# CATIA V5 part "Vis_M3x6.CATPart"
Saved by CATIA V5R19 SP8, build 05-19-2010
Part number: Vis M3x6
Nomenclature:  MAKER100359
Publications: "Mating Face", "Axis"
Bounding box of the stored display mesh (mm): x -6 to 1.764, y -3.2 to 3.2, z -3.2 to 3.2
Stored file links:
  D:\Documents\1_Travail\1 - ac-limoges.fr\ac-limoges.fr\Emmanuel Maynard - STI2D_Turgot\1 - IT-I2D\Activités_IT_Première\IT_3_Abris_bus\Maquettes numériques\Abribus_eleve\Vis_M3x6.CATPart
  C:\Program Files\Dassault Systemes\B19\win_b64\startup\components\MechanicalStandardParts\EN_Standards\Design_Tables\EN_ISO_4762_HEXAGON_SOCKET_HEAD_CAP_SCREW.txt
  C:\Program Files\Dassault Systemes\B19\win_b64\startup\components\MechanicalStandardParts\ISO_Standards\Design_Tables\ISO_4762_HEXAGON_SOCKET_HEAD_CAP_SCREW.txt
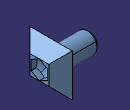
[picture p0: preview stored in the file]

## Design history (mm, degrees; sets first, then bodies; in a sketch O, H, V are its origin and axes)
Parameters
  d_dia = 3 mm
  l_nom = 6 mm
  k_head_depth_max = 3 mm
  s_nom = 2.5 mm
  r_min = 0.1 mm
  ds_max = 3 mm
  e = 2.873 mm
  t_min = 1.3 mm
  p_pitch = 0.5 mm
  Threading = 4.5 mm
  dk_max = 5.5 mm
Set1
  Plane1: type Offset, RefPlane start face of Pad1, Offset 0.5
  Plane2: type OffsetPt, RefPlane Plane1, RefPoint vertex [face of Pad2 from Sketch3.L3 | face of Pad1 from Sketch1.L4 | face of Shaft2 from Sketch4.L2]
Body1 "PartBody" (main body)
  Sketch1 on yz-plane, origin (0, 0, 0), H (0, 1, 0), V (0, 0, 1)
    line L1 (2.7, 2.7) -> (2.7, -2.7)
    line L2 (2.7, -2.7) -> (-2.7, -2.7)
    line L3 (-2.7, -2.7) -> (-2.7, 2.7)
    line L4 (-2.7, 2.7) -> (2.7, 2.7)
    distance L4 L2 = 5.4
    distance L1 L3 = 5.4
    vertical: L1 V, L3 V
    horizontal: L2 H, L4 H
    equidistance: L1 L3 O, L2 L4 O
  Pad1: profile Sketch1, direction (1, 0, 0), length 3 {= k_head_depth_max}
  Sketch2 on xy-plane, origin (0, 0, 0), H (1, 0, 0), V (0, 1, 0)
    line L1 (0, 0) -> (0, 1.5)
    line L2 (0, 1.5) -> (-1.5, 1.5)
    line L3 (-1.5, 1.5) -> (-1.5, 1.4634)
    line L4 (-1.5, 1.4634) -> (-6, 1.4634)
    line L5 (-6, 1.4634) -> (-6, 0)
    axis line L6 (-192.3446, 0) -> (99.1594, 0)
    distance L5 L1 = 6 {= l_nom}
    distance L3 L5 = 4.5 {= Threading}
    distance L2 L6 = 1.5 {= ds_max /2}
    distance L4 L6 = 1.4634 {= d_dia /2.05}
    vertical: L1 V, L3 V, L5 V
    horizontal: L2 H, L4 H, L6 H
    fix: L6
  Shaft1: profile Sketch2, axis Sketch2.L6, angle 360
  Fillet1: radius 0.1 {= r_min}, on edge [face of Shaft1 | face of Pad1]
  Chamfer1: length 0.5 {= p_pitch}, angle 45, on edge [face of Shaft1 | face of Shaft1]
  Thread1: diameter 2.9268 {= d_dia /1.025}, depth 4.5 {= Threading}, pitch 1, on face of Shaft1, from face of Shaft1
  Draft1: PullDir start face of Pad1, Angle -45, SupportToDraft (face of Pad1 from Sketch1.L1; face of Pad1 from Sketch1.L2; face of Pad1 from Sketch1.L3; face of Pad1 from Sketch1.L4), Neutral Plane1
  Body2
    Sketch3 on face of Pad1, origin (3, 0, 0), H (0, 1, 0), V (0, 0, 1)
      point P1 (1.25, -0.7217)
      point P2 (1.25, 0.7217)
      point P3 (0, 1.4434)
      point P4 (-1.25, 0.7217)
      point P5 (-1.25, -0.7217)
      point P6 (0, -1.4434)
      point P7 (1.25, 0)
      line L1 (1.25, -0.7217) -> (1.25, 0.7217)
      line L2 (1.25, 0.7217) -> (0, 1.4434)
      line L3 (0, 1.4434) -> (-1.25, 0.7217)
      line L4 (-1.25, 0.7217) -> (-1.25, -0.7217)
      line L5 (-1.25, -0.7217) -> (0, -1.4434)
      line L6 (0, -1.4434) -> (1.25, -0.7217)
      construction line L7 (0, 0) -> (1.25, 0)
      construction circle A1 centre (0, 0) radius 1.4434
      construction arc A2 centre (-1.25, -0.7217) radius 1.4434 from (-1.25, 0.7217) to (0, -1.4434) cw
      construction arc A3 centre (1.25, 0.7217) radius 1.4434 from (0, 1.4434) to (1.25, -0.7217) ccw
      point P8 (-1.25, -0.7217)
      point P9 (1.25, 0.7217)
      distance L1 L4 = 2.5 {= s_nom}
      horizontal: L7 H
      coincidence: A1 P1, A1 P2, A1 P3, A1 P4, A1 P5, A1 P6, A2 P4, A2 P6, A2 O, P8 P5, A3 P3, A3 P1, A3 O, P9 P2
      midpoint: P7 L1
    Pad2: profile Sketch3, direction (-1, 0, 0), length 3
    Body3
      Sketch4 on zx-plane, origin (0, 0, 0), H (-1, 0, 0), V (0, 0, 1)
        point P1 (-0.1706, 0)
        line L1 (-0.1706, 0) -> (-1, 1.4365)
        line L2 (-1, 1.4365) -> (-3, 1.4365)
        line L3 (-3, 1.4365) -> (-3, 0)
        axis line L4 (-46.2384, 0) -> (26.3409, 0)
        reference projected line E1 (-3, -6.9227) -> (-3, 6.9227) from edge [face of Pad2 | face of Pad2]
        length L2 = 2
        angle L1 L4 = 60
        distance L2 L4 = 1.4365 {= e /2}
        horizontal: L2 H, L4 H
        perpendicularity: L3 L2
        fix: L4
        coincidence: L3 E1, P1 L4
      Shaft2: profile Sketch4, axis Sketch4.L4, angle 360
    Intersect1: tool Body3
  Remove1: tool Body2
  Split1: SplitPlane Plane2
